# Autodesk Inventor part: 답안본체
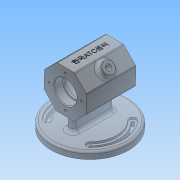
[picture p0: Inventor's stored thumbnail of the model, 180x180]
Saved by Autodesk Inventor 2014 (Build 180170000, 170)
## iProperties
Created: 2017-06
Part Number: 답안본체
Material: 일반
Document SubType Name: Modeling
Designer: NET
Density: 1 g/cm^3
Appearance: 기본값
Author: NET
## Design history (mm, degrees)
sketch "스케치1"
  geometry: C1 r 55 at (0, 0); 1 further point
  constraints: 1 centre point, 1 coincident
  dimensions: "d0" = 110 diameter of C1
extrude "돌출1" new body sketch "스케치1" distance "d1" = 10; taper "d2" = 0 deg
sketch "스케치2"
  geometry: L1 (0, 0)-(0, 62); L2 (0, 62)-(-35, 62); L3 (-35, 62)-(-35, 92); L4 (-35, 92)-(35, 92); L5 (35, 92)-(35, 62); L6 (35, 62)-(0, 62); L7 (-35, 62)-(-23, 62); L8 (-23, 62)-(-23, 77.7); L9 (-23.3, 78)-(-35, 78); L10 (0, 62)-(-20, 62); L11 (-20, 62)-(-20, 84); L12 (-17, 87)-(17, 87); L13 (20, 84)-(20, 62); L14 (35, 62)-(23, 62); L15 (23, 62)-(23, 77.7); L16 (23.3, 78)-(35, 78); L17 (23, 62)-(23, 76); L18 (23, 76)-(20, 76); L19 (-23, 62)-(-23, 76); L20 (-23, 76)-(-20, 76); A1 r 3 centre (-17, 84) between (-17, 87) and (-20, 84); A2 r 3 centre (17, 84) between (20, 84) and (17, 87); A3 r 0.3 centre (-23.3, 77.7) between (-23, 77.7) and (-23.3, 78); A4 r 0.3 centre (23.3, 77.7) between (23.3, 78) and (23, 77.7); 4 further points
  constraints: 40 end point, 18 point on line, 10 perpendicular, 8 point on circle, 8 tangent, 4 centre point, 4 parallel, 2 equal radius, 1 vertical
  dimensions: "d3" = 62 distance of L1.start L1.end; "d4" = 35 distance of L1.end L2.end; "d5" = 30 distance of L2.end L3.end; "d6" = 70 distance of L3.end L4.end; "d7" = 12 distance of L2.end L7.end; "d8" = 16 distance of L7.end point (-23, 78); "d9" = 20 distance of L1.end L10.end; "d10" = 25 distance of L10.end point (-20, 87); "d11" = 40 distance of point (-20, 87) point (20, 87); "d12" = 12 distance of L5.end L14.end; "d13" = 16 distance of L14.end point (23, 78); "d14" = 14 distance of L14.end L17.end; "d15" = 14 distance of L7.end L19.end; "d16" = 3 radius of A1; "d102" = 0.3 radius of A3
revolve "회전1" sketch "스케치2" stored, may be unused: angle "d17" = 90 deg
sketch "스케치3"
  geometry: L1 (0, 0)-(0, 50); L2 (0, 0)-(-16.273, 39.288); L3 (0, 30)-(-12.426, 30); L4 (17.179, 30.081)-(34.641, 0.163); L5 (34.641, 0.163)-(17.462, -29.918); L6 (17.462, -29.918)-(-17.179, -30.081); L7 (-17.179, -30.081)-(-34.641, -0.163); L8 (-34.641, -0.163)-(-17.462, 29.918); L9 (-17.462, 29.918)-(17.179, 30.081); 2 further points
  constraints: 18 end point, 2 point on line, 1 coincident, 1 horizontal, 1 perpendicular, 1 vertical, 1 vertical alignment, 14 other
  dimensions: "d18" = 50 distance of L1.start L1.end; "d19" = 22.5 deg angle of L1 L2; "d20" = 30 distance from line of L9 point (0, 0); "d21" = 17.17898 horizontal distance of L7.end L8.end
extrude "돌출2" join sketch "스케치3" distance "d22" = 70; taper "d23" = 0 deg
sketch "스케치5"
  geometry: L1 (0, 0)-(0, -24); L2 (0, 0)-(0, 24); L3 (-5, -24)-(-5, 24); L4 (5, -24)-(5, 24); C1 r 55 at (0, 0) reference; A1 r 5 centre (0, -24) between (-5, -24) and (5, -24); A2 r 5 centre (0, 24) between (-5, 24) and (5, 24)
  constraints: 8 end point, 4 point on circle, 2 centre point, 2 coincident, 2 equal length, 2 tangent, 1 vertical
  dimensions: "d58" = 24 distance of L1.start L1.end; "d59" = 10 diameter of A1; "d60" = 24 distance of L1.start L2.end; "d61" = 10 diameter of A2; "d62" = 10 distance between parallel lines of L4 L3
extrude "돌출4" join sketch "스케치5" stored distance "d63" = 10; taper "d64" = 0 deg
sketch "스케치6"
  geometry: L1 (30, -17.321)-(0, 0) reference; L2 (30, 51.962)-(60, 34.641) reference; L3 (45, 43.301)-(15, -8.66); L4 (0, 34.641)-(60, 0); C1 r 16 at (30, 17.321) reference; C2 r 2.5 at (41.5, 37.239); C3 r 2.5 at (10.081, 28.821); C4 r 2.5 at (18.5, -2.598); C5 r 2.5 at (49.919, 5.821); A1 r 23 centre (30, 17.321) between (41.5, 37.239) and (10.081, 28.821); 1 further point
  constraints: 5 centre point, 4 end point, 4 point on circle, 4 point on line, 2 midpoint, 1 coincident, 1 perpendicular
  dimensions: "d66" = 46 diameter of A1; "d67" = 5 diameter of C2; "d68" = 5 diameter of C3; "d69" = 5 diameter of C4; "d70" = 5 diameter of C5
hole "구멍1" sketch "스케치6" at (41.5, 37.239), (10.081, 28.821), (18.5, -2.598), (49.919, 5.821) diameter "d71" = 3.242; stored, may be unused: countersink angle "d75" = 90 deg, drill point angle "d77" = 118 deg; dims "d72" = 8, "d73" = 4, "d74" = 2, "d76" = 10
sketch "스케치7" dims "d78" = 46
  geometry: L1 (0, 0)-(30, -17.321) reference; L2 (60, 34.641)-(30, 51.962) reference; L3 (45, 43.301)-(15, -8.66); L4 (0, 34.641)-(60, 0); C1 r 16 at (30, 17.321) reference; C2 r 2 at (18.5, -2.598); C3 r 2 at (49.919, 5.821); C4 r 2 at (41.5, 37.239); C5 r 2 at (10.081, 28.821); 2 further points
  constraints: 4 centre point, 4 end point, 2 midpoint, 1 coincident, 1 perpendicular, 1 point on line, 12 other
  dimensions: "d79" = 4 diameter of C2; "d82" = 360 deg dimension on point (30, 17.321) C2.centre (derived)
hole "구멍2" sketch "스케치7" at (18.5, -2.598), (49.919, 5.821), (41.5, 37.239), (10.081, 28.821) diameter "d84" = 3.242; stored, may be unused: countersink angle "d88" = 90 deg, drill point angle "d90" = 118 deg; dims "d85" = 8, "d86" = 4, "d87" = 2, "d89" = 10
sketch "스케치8"
  geometry: L1 (0, 0)-(0, 70) reference; L2 (0, 0)-(0, 35); L3 (-17.321, 70)-(0, 70) reference; L4 (-17.321, 0)-(-17.321, 70) reference; L5 (-17.321, 0)-(0, 0) reference; L6 (0, 0)-(0, 70) reference; L7 (-17.321, 35)-(17.679, 35); 2 further points
  constraints: 4 end point, 2 midpoint, 1 coincident, 1 perpendicular, 1 other
  dimensions: "d91" = 35 distance of L1.start L2.end; "d92" = 35 distance of L7.start L7.end
feature "엠보싱1" sketch "스케치8" dims "d1" = 10, "d2" = 0, "d3" = 62, "d4" = 35, "d5" = 30, "d6" = 70, "d7" = 12, "d8" = 16, "d9" = 20, "d10" = 25, "d11" = 40, "d12" = 12, "d13" = 16, "d14" = 14, "d15" = 14, "d16" = 3, "d93" = 0.5, "d94" = 0, "d102" = 0.3
sketch "스케치11" dims "d117" = 4, "d118" = 4, "d119" = 4
  geometry: L1 (-5, -24)-(-5, 24) reference; L2 (-55, 0)-(55, 0); L3 (-26.87, 26.87)-(-45.953, 45.953); L4 (-26.87, -26.87)-(-33.941, -33.941); L5 (26.87, 26.87)-(33.941, 33.941); L6 (26.87, -26.87)-(33.941, -33.941); C1 r 48 at (0, 0); C2 r 5 at (-30.406, 30.406); A1 r 55 centre (0, 0) between (-55, 0) and (55, 0) reference; A2 r 5 centre (-30.406, -30.406) between (-33.941, -33.941) and (-26.87, -26.87); A3 r 5 centre (30.406, -30.406) between (26.87, -26.87) and (33.941, -33.941); A4 r 5 centre (30.406, 30.406) between (33.941, 33.941) and (26.87, 26.87); A5 r 2 centre (-30.406, -30.406) between (-28.991, -28.991) and (-28.959, -31.787); A6 r 38 centre (0, 0) between (26.87, -26.87) and (26.87, 26.87); A7 r 38 centre (0, 0) between (-26.87, 26.87) and (-26.87, -26.87); A8 r 41 centre (0, 0) between (28.991, -28.991) and (28.991, 28.991); A9 r 41 centre (0, 0) between (-28.991, 28.991) and (-28.991, -28.991); A10 r 43 centre (0, 0) between (28.959, -31.787) and (28.959, 31.787); A11 r 43 centre (0, 0) between (-28.959, 31.787) and (-28.959, -31.787); A12 r 45 centre (0, 0) between (31.82, -31.82) and (31.82, 31.82); A13 r 45 centre (0, 0) between (-31.82, 31.82) and (-31.82, -31.82); 4 further points
  constraints: 31 point on circle, 14 centre point, 10 coincident, 10 end point, 7 point on line, 3 midpoint, 1 perpendicular, 9 other
  dimensions: "d105" = 96 diameter of C1; "d106" = 110 distance of L2.start L2.end; "d108" = 10 diameter of A2; "d113" = 10 diameter of A3; "d115" = 10 diameter of A4; "d116" = 4 diameter of A5; "d122" = 19.08317 horizontal distance of L3.start L3.end; "d125" = 19.08317 horizontal distance of L3.start L3.end; "d127" = 38 radius of A6; "d128" = 41 radius of A8; "d129" = 43 radius of A10; "d130" = 45 radius of A12; "d131" = 38 radius of A7; "d132" = 41 radius of A9; "d133" = 43 radius of A11; "d134" = 45 radius of A13
extrude "돌출7" cut sketch "스케치11" stored distance "d135" = 7; taper "d136" = 0 deg
sketch "스케치12"
  geometry: L1 (-5, -24)-(-5, 24) reference; L2 (0, -55)-(0, 55); L3 (-55, 0)-(55, 0); L4 (28.991, -28.991)-(31.82, -31.82); L5 (28.991, 28.991)-(31.82, 31.82); A1 r 45 centre (0, 0) between (-31.82, 31.82) and (-31.82, -31.82) reference; A2 r 2 centre (-30.406, 30.406) between (-28.991, 28.991) and (-31.82, 31.82) reference; A3 r 2 centre (-30.406, -30.406) between (-31.82, -31.82) and (-28.991, -28.991) reference; A4 r 55 centre (0, 0) between (0, -55) and (0, 55) reference; A5 r 2 centre (30.406, -30.406) between (28.991, -28.991) and (31.82, -31.82); A6 r 2 centre (30.406, 30.406) between (31.82, 31.82) and (28.991, 28.991); A7 r 41 centre (0, 0) between (-28.991, 28.991) and (-28.991, -28.991); A8 r 41 centre (0, 0) between (28.991, -28.991) and (28.991, 28.991); A9 r 41 centre (0, 0) between (-28.991, 28.991) and (-28.991, -28.991); A10 r 45 centre (0, 0) between (31.82, -31.82) and (31.82, 31.82)
  constraints: 20 point on circle, 8 end point, 6 centre point, 2 coincident, 2 midpoint, 1 parallel, 1 perpendicular
  dimensions: "d137" = 110 distance of L2.start L2.end; "d141" = 4 diameter of A6; "d142" = 4 diameter of A5; "d143" = 110 distance of L3.start L3.end; "d144" = 30.40559 horizontal distance of A1.centre A5.centre; "d145" = 30.40559 distance from line of A6.centre L2; "d147" = 30.40559 distance from line of L3 A5.centre; "d148" = 41 radius of A8; "d149" = 45 radius of A10
extrude "돌출8" cut sketch "스케치12" stored distance "d150" = 7; taper "d151" = 0 deg
sketch "스케치13"
  geometry: C1 r 55 at (0, 0) reference; A1 r 45 centre (0, 0) between (31.82, -31.82) and (31.82, 31.82) reference; A2 r 2 centre (30.406, -30.406) between (28.991, -28.991) and (31.82, -31.82) reference; A3 r 41 centre (0, 0) between (28.991, -28.991) and (28.991, 28.991) reference; A4 r 2 centre (30.406, 30.406) between (31.82, 31.82) and (28.991, 28.991) reference; A5 r 2 centre (-30.406, 30.406) between (-28.991, 28.991) and (-31.82, 31.82) reference; A6 r 2 centre (-30.406, -30.406) between (-31.82, -31.82) and (-28.991, -28.991) reference; A7 r 5 centre (-30.406, -30.406) between (-26.87, -26.87) and (-33.941, -33.941); A8 r 5 centre (-30.406, 30.406) between (-26.87, 26.87) and (-33.941, 33.941); A9 r 5 centre (30.406, 30.406) between (26.87, 26.87) and (33.941, 33.941); A10 r 5 centre (30.406, -30.406) between (26.87, -26.87) and (33.941, -33.941); A11 r 38 centre (0, 0) between (26.87, -26.87) and (26.87, 26.87); A12 r 38 centre (0, 0) between (-26.87, 26.87) and (-26.87, -26.87); A13 r 48 centre (0, 0) between (33.941, -33.941) and (33.941, 33.941); A14 r 48 centre (0, 0) between (-33.941, 33.941) and (-33.941, -33.941)
  constraints: 16 point on circle, 8 centre point, 6 coincident
  dimensions: "d154" = 10 diameter of A7; "d155" = 10 diameter of A8; "d156" = 10 diameter of A9; "d157" = 10 diameter of A10; "d158" = 38 radius of A12; "d159" = 38 radius of A11; "d160" = 48 radius of A13; "d161" = 48 radius of A14
extrude "돌출9" cut sketch "스케치13" distance "d162" = 3; taper "d163" = 0 deg
chamfer "모따기1" distance "d164" = 1; stored, may be unused: second distance "d165" = 2, angle "d166" = 45 deg
chamfer "모따기2" distance "d167" = 1; stored, may be unused: second distance "d168" = 2, angle "d169" = 45 deg
fillet "모깎기1" dims "d170" = 1
fillet "모깎기2" dims "d171" = 3
fillet "모깎기3" dims "d172" = 5
sketch "스케치14"
  geometry: L1 (0, 0)-(0, 33.486) reference; L2 (29.5, -17.609)-(0.5, -0.866) reference; L3 (59.5, -0.866)-(30.5, -17.609) reference; L4 (60, 33.486)-(60, 0) reference; L5 (30.5, 51.095)-(59.5, 34.352) reference; L6 (0.5, 34.352)-(29.5, 51.095) reference; C1 r 17 at (30, 16.743) reference; C2 r 30 at (30, 16.743); A1 r 1 centre (1, 33.486) between (0.5, 34.352) and (0, 33.486) reference; A2 r 1 centre (1, 0) between (0, 0) and (0.5, -0.866) reference; A3 r 1 centre (30, -16.743) between (29.5, -17.609) and (30.5, -17.609) reference; A4 r 1 centre (59, 0) between (59.5, -0.866) and (60, 0) reference; A5 r 1 centre (59, 33.486) between (60, 33.486) and (59.5, 34.352) reference; A6 r 1 centre (30, 50.229) between (30.5, 51.095) and (29.5, 51.095) reference; 1 further point
  constraints: 1 centre point, 1 coincident
extrude "돌출10" cut sketch "스케치14" stored distance "d174" = 0; taper "d175" = 0 deg
sketch "스케치15"
  geometry: L1 (12.786, 29.848)-(30.147, 12.065); L2 (30.147, 12.065)-(29.848, -12.786); L3 (29.848, -12.786)-(12.065, -30.147); L4 (12.065, -30.147)-(-12.786, -29.848); L5 (-12.786, -29.848)-(-30.147, -12.065); L6 (-30.147, -12.065)-(-29.848, 12.786); L7 (-29.848, 12.786)-(-12.065, 30.147); L8 (-12.065, 30.147)-(12.786, 29.848); C1 r 30 at (0, 0) reference; C2 r 17 at (0, 0) reference; 2 further points
  constraints: 16 end point, 1 coincident, 17 other
  dimensions: "d176" = 30 distance from line of point (0, 0) L8
extrude "돌출11" join sketch "스케치15" distance "d177" = 70; taper "d178" = 0 deg
sketch "스케치16"
  geometry: L1 (0, 0)-(24.853, 0) reference; L2 (24.853, 0)-(24.853, 70) reference; L3 (12.426, 0)-(12.426, 35); C1 r 8 at (12.426, 35); 1 further point
  constraints: 2 end point, 1 centre point, 1 coincident, 1 midpoint, 1 parallel
  dimensions: "d180" = 35 distance of L3.start L3.end; "d181" = 16 diameter of C1
extrude "돌출12" join sketch "스케치16" distance "d182" = 7; taper "d183" = 0 deg
sketch "스케치17"
  geometry: C1 r 8 at (0, 0) reference; C2 r 4 at (0, 0); 1 further point
  constraints: 1 centre point, 1 coincident
  dimensions: "d184" = 8 diameter of C2
extrude "돌출13" cut sketch "스케치17" stored distance "d185" = 7; taper "d186" = 0 deg
fillet "모깎기5" dims "d187" = 5
fillet "모깎기6" dims "d188" = 2
fillet "모깎기7" dims "d189" = 2
node "솔리드1"
node "투영된 루프2"
other parameters: "d24" = 86, "d25" = 96, "d26" = 76, "d28" = 45 deg, "d29" = 45 deg, "d34" = 43, "d35" = 43, "d50" = 86, "d103" = 86, "d104" = 76, "d107" = 45 deg, "d109" = 45 deg, "d112" = 45 deg, "d114" = 45 deg, "d121" = 82, "d139" = 45 deg, "d140" = 45 deg, "d152" = 96, "d153" = 76
